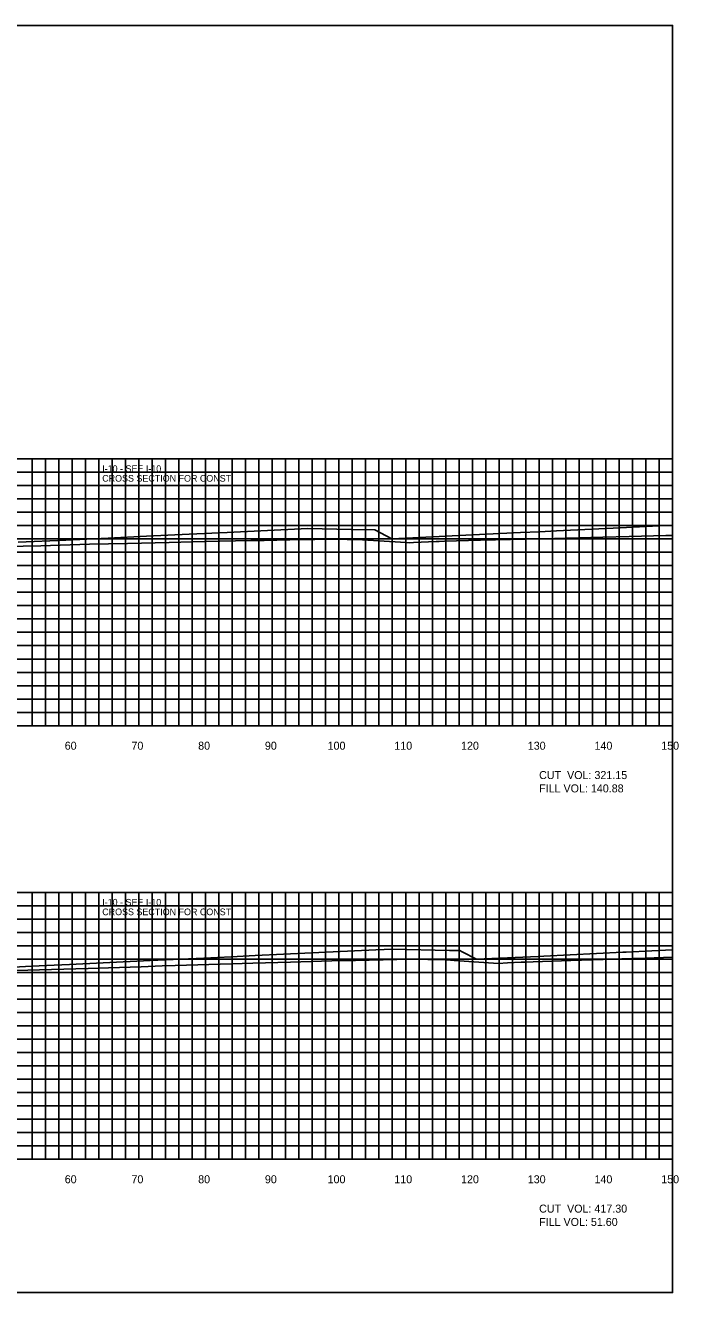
# Model space of a CAD drawing. Extents: x 1797652 to 1804159, y 242516 to 246906.
# Drawn here: x 1803717.5 to 1803815.4, y 242516 to 242706 of the extents above; entities that cross this region are included whole.
import ezdxf

# ---------------------------------------------------------------- set-up
doc = ezdxf.new("R2010")
doc.units = 0
for name, color, linetype in [('10', 7, 'Continuous'), ('3', 7, 'Continuous'), ('60', 7, 'Continuous'), ('CL-CNST', 7, 'Continuous'), ('Level 62', 7, 'Continuous'), ('M-ROADS', 7, 'Continuous')]:
    doc.layers.add(name, color=color, linetype=linetype)

msp = doc.modelspace()

# ---------------------------------------------------------------- linework, layer by layer
msp.add_lwpolyline([(1803514.49, 242516), (1803814.49, 242516), (1803814.49, 242706), (1803514.49, 242706)], close=True)
at = {"layer": '60'}
for p, q in [((1803814.49, 242601), (1803814.49, 242641)), ((1803814.55, 242641), (1803814.49, 242641)), ((1803814.55, 242631), (1803814.49, 242631)), ((1803814.55, 242621), (1803814.49, 242621)), ((1803814.55, 242611), (1803814.49, 242611)), ((1803514.49, 242601), (1803814.49, 242601)), ((1803724.49, 242600.94), (1803724.49, 242601)), ((1803734.49, 242600.94), (1803734.49, 242601)), ((1803744.49, 242600.94), (1803744.49, 242601)), ((1803754.49, 242600.94), (1803754.49, 242601)), ((1803764.49, 242600.94), (1803764.49, 242601)), ((1803774.49, 242600.94), (1803774.49, 242601)), ((1803784.49, 242600.94), (1803784.49, 242601)), ((1803794.49, 242600.94), (1803794.49, 242601)), ((1803804.49, 242600.94), (1803804.49, 242601)), ((1803814.49, 242600.94), (1803814.49, 242601)), ((1803814.55, 242601), (1803814.49, 242601)), ((1803814.49, 242536), (1803814.49, 242576)), ((1803814.55, 242576), (1803814.49, 242576)), ((1803814.55, 242566), (1803814.49, 242566)), ((1803814.55, 242556), (1803814.49, 242556)), ((1803814.55, 242546), (1803814.49, 242546)), ((1803514.49, 242536), (1803814.49, 242536)), ((1803724.49, 242535.94), (1803724.49, 242536)), ((1803734.49, 242535.94), (1803734.49, 242536)), ((1803744.49, 242535.94), (1803744.49, 242536)), ((1803754.49, 242535.94), (1803754.49, 242536)), ((1803764.49, 242535.94), (1803764.49, 242536)), ((1803774.49, 242535.94), (1803774.49, 242536)), ((1803784.49, 242535.94), (1803784.49, 242536)), ((1803794.49, 242535.94), (1803794.49, 242536)), ((1803804.49, 242535.94), (1803804.49, 242536)), ((1803814.49, 242535.94), (1803814.49, 242536)), ((1803814.55, 242536), (1803814.49, 242536))]:
    msp.add_line(p, q, dxfattribs=at)
at = {"layer": 'CL-CNST'}
for points in [[(1803716.41, 242628.5), (1803723.57, 242628.84), (1803729.92, 242629.14), (1803735.65, 242629.42), (1803742.06, 242629.72), (1803747.74, 242629.99), (1803752.78, 242630.23), (1803759.82, 242630.57), (1803766.31, 242630.42), (1803769.89, 242630.35), (1803770.73, 242629.91), (1803772.41, 242629.04), (1803775.54, 242629.19), (1803782.48, 242629.52), (1803791.69, 242629.96), (1803794.56, 242630.09), (1803797.11, 242630.22), (1803806.65, 242630.67), (1803808.56, 242630.76), (1803814.49, 242631.04)], [(1803712.02, 242564.62), (1803718.41, 242564.93), (1803724.12, 242565.2), (1803729.14, 242565.44), (1803736.22, 242565.78), (1803744.22, 242566.16), (1803748.32, 242566.35), (1803751.92, 242566.53), (1803760.42, 242566.93), (1803770.01, 242567.39), (1803772.52, 242567.51), (1803781.07, 242567.32), (1803782.6, 242567.29), (1803782.95, 242567.1), (1803785.12, 242565.98), (1803794.35, 242566.42), (1803795.2, 242566.46), (1803807.04, 242567.03), (1803807.3, 242567.04), (1803807.53, 242567.05), (1803811.36, 242567.23), (1803814.49, 242567.38)]]:
    msp.add_lwpolyline(points, dxfattribs=at)
at = {"layer": 'Level 62'}
for p, q in [((1803514.49, 242641), (1803814.49, 242641)), ((1803718.49, 242601), (1803718.49, 242641)), ((1803720.49, 242601), (1803720.49, 242641)), ((1803722.49, 242601), (1803722.49, 242641)), ((1803724.49, 242601), (1803724.49, 242641)), ((1803726.49, 242601), (1803726.49, 242641)), ((1803728.49, 242601), (1803728.49, 242641)), ((1803730.49, 242601), (1803730.49, 242641)), ((1803732.49, 242601), (1803732.49, 242641)), ((1803734.49, 242601), (1803734.49, 242641)), ((1803736.49, 242601), (1803736.49, 242641)), ((1803738.49, 242601), (1803738.49, 242641)), ((1803740.49, 242601), (1803740.49, 242641)), ((1803742.49, 242601), (1803742.49, 242641)), ((1803744.49, 242601), (1803744.49, 242641)), ((1803746.49, 242601), (1803746.49, 242641)), ((1803748.49, 242601), (1803748.49, 242641)), ((1803750.49, 242601), (1803750.49, 242641)), ((1803752.49, 242601), (1803752.49, 242641)), ((1803754.49, 242601), (1803754.49, 242641)), ((1803756.49, 242601), (1803756.49, 242641)), ((1803758.49, 242601), (1803758.49, 242641)), ((1803760.49, 242601), (1803760.49, 242641)), ((1803762.49, 242601), (1803762.49, 242641)), ((1803764.49, 242601), (1803764.49, 242641)), ((1803766.49, 242601), (1803766.49, 242641)), ((1803768.49, 242601), (1803768.49, 242641)), ((1803770.49, 242601), (1803770.49, 242641)), ((1803772.49, 242601), (1803772.49, 242641)), ((1803774.49, 242601), (1803774.49, 242641)), ((1803776.49, 242601), (1803776.49, 242641)), ((1803778.49, 242601), (1803778.49, 242641)), ((1803780.49, 242601), (1803780.49, 242641)), ((1803782.49, 242601), (1803782.49, 242641)), ((1803784.49, 242601), (1803784.49, 242641)), ((1803786.49, 242601), (1803786.49, 242641)), ((1803788.49, 242601), (1803788.49, 242641)), ((1803790.49, 242601), (1803790.49, 242641)), ((1803792.49, 242601), (1803792.49, 242641)), ((1803794.49, 242601), (1803794.49, 242641)), ((1803796.49, 242601), (1803796.49, 242641)), ((1803798.49, 242601), (1803798.49, 242641)), ((1803800.49, 242601), (1803800.49, 242641)), ((1803802.49, 242601), (1803802.49, 242641)), ((1803804.49, 242601), (1803804.49, 242641)), ((1803806.49, 242601), (1803806.49, 242641)), ((1803808.49, 242601), (1803808.49, 242641)), ((1803810.49, 242601), (1803810.49, 242641)), ((1803812.49, 242601), (1803812.49, 242641)), ((1803814.49, 242601), (1803814.49, 242641)), ((1803514.49, 242639), (1803814.49, 242639)), ((1803514.49, 242637), (1803814.49, 242637)), ((1803514.49, 242635), (1803814.49, 242635)), ((1803514.49, 242633), (1803814.49, 242633)), ((1803514.49, 242631), (1803814.49, 242631)), ((1803514.49, 242629), (1803814.49, 242629)), ((1803514.49, 242627), (1803814.49, 242627)), ((1803514.49, 242625), (1803814.49, 242625)), ((1803514.49, 242623), (1803814.49, 242623)), ((1803514.49, 242621), (1803814.49, 242621)), ((1803514.49, 242619), (1803814.49, 242619)), ((1803514.49, 242617), (1803814.49, 242617)), ((1803514.49, 242615), (1803814.49, 242615)), ((1803514.49, 242613), (1803814.49, 242613)), ((1803514.49, 242611), (1803814.49, 242611)), ((1803514.49, 242609), (1803814.49, 242609)), ((1803514.49, 242607), (1803814.49, 242607)), ((1803514.49, 242605), (1803814.49, 242605)), ((1803514.49, 242603), (1803814.49, 242603)), ((1803514.49, 242601), (1803814.49, 242601)), ((1803514.49, 242576), (1803814.49, 242576)), ((1803718.49, 242536), (1803718.49, 242576)), ((1803720.49, 242536), (1803720.49, 242576)), ((1803722.49, 242536), (1803722.49, 242576)), ((1803724.49, 242536), (1803724.49, 242576)), ((1803726.49, 242536), (1803726.49, 242576)), ((1803728.49, 242536), (1803728.49, 242576)), ((1803730.49, 242536), (1803730.49, 242576)), ((1803732.49, 242536), (1803732.49, 242576)), ((1803734.49, 242536), (1803734.49, 242576)), ((1803736.49, 242536), (1803736.49, 242576)), ((1803738.49, 242536), (1803738.49, 242576)), ((1803740.49, 242536), (1803740.49, 242576)), ((1803742.49, 242536), (1803742.49, 242576)), ((1803744.49, 242536), (1803744.49, 242576)), ((1803746.49, 242536), (1803746.49, 242576)), ((1803748.49, 242536), (1803748.49, 242576)), ((1803750.49, 242536), (1803750.49, 242576)), ((1803752.49, 242536), (1803752.49, 242576)), ((1803754.49, 242536), (1803754.49, 242576)), ((1803756.49, 242536), (1803756.49, 242576)), ((1803758.49, 242536), (1803758.49, 242576)), ((1803760.49, 242536), (1803760.49, 242576)), ((1803762.49, 242536), (1803762.49, 242576)), ((1803764.49, 242536), (1803764.49, 242576)), ((1803766.49, 242536), (1803766.49, 242576)), ((1803768.49, 242536), (1803768.49, 242576)), ((1803770.49, 242536), (1803770.49, 242576)), ((1803772.49, 242536), (1803772.49, 242576)), ((1803774.49, 242536), (1803774.49, 242576)), ((1803776.49, 242536), (1803776.49, 242576)), ((1803778.49, 242536), (1803778.49, 242576)), ((1803780.49, 242536), (1803780.49, 242576)), ((1803782.49, 242536), (1803782.49, 242576)), ((1803784.49, 242536), (1803784.49, 242576)), ((1803786.49, 242536), (1803786.49, 242576)), ((1803788.49, 242536), (1803788.49, 242576)), ((1803790.49, 242536), (1803790.49, 242576)), ((1803792.49, 242536), (1803792.49, 242576)), ((1803794.49, 242536), (1803794.49, 242576)), ((1803796.49, 242536), (1803796.49, 242576)), ((1803798.49, 242536), (1803798.49, 242576)), ((1803800.49, 242536), (1803800.49, 242576)), ((1803802.49, 242536), (1803802.49, 242576)), ((1803804.49, 242536), (1803804.49, 242576)), ((1803806.49, 242536), (1803806.49, 242576)), ((1803808.49, 242536), (1803808.49, 242576)), ((1803810.49, 242536), (1803810.49, 242576)), ((1803812.49, 242536), (1803812.49, 242576)), ((1803814.49, 242536), (1803814.49, 242576)), ((1803514.49, 242574), (1803814.49, 242574)), ((1803514.49, 242572), (1803814.49, 242572)), ((1803514.49, 242570), (1803814.49, 242570)), ((1803514.49, 242568), (1803814.49, 242568)), ((1803514.49, 242566), (1803814.49, 242566)), ((1803514.49, 242564), (1803814.49, 242564)), ((1803514.49, 242562), (1803814.49, 242562)), ((1803514.49, 242560), (1803814.49, 242560)), ((1803514.49, 242558), (1803814.49, 242558)), ((1803514.49, 242556), (1803814.49, 242556)), ((1803514.49, 242554), (1803814.49, 242554)), ((1803514.49, 242552), (1803814.49, 242552)), ((1803514.49, 242550), (1803814.49, 242550)), ((1803514.49, 242548), (1803814.49, 242548)), ((1803514.49, 242546), (1803814.49, 242546)), ((1803514.49, 242544), (1803814.49, 242544)), ((1803514.49, 242542), (1803814.49, 242542)), ((1803514.49, 242540), (1803814.49, 242540)), ((1803514.49, 242538), (1803814.49, 242538)), ((1803514.49, 242536), (1803814.49, 242536))]:
    msp.add_line(p, q, dxfattribs=at)
at = {"layer": 'M-ROADS'}
for points in [[(1803714.52, 242627.85), (1803719.8, 242627.99), (1803727.11, 242628.2), (1803732.82, 242628.33), (1803739.05, 242628.49), (1803744.32, 242628.61), (1803751.3, 242628.75), (1803753.27, 242628.79), (1803757.11, 242628.86), (1803760.89, 242628.92), (1803762.84, 242628.96), (1803763.71, 242628.96), (1803764.09, 242628.97), (1803765.71, 242628.92), (1803768, 242628.85), (1803773.72, 242628.52), (1803775.1, 242628.44), (1803775.66, 242628.46), (1803779.04, 242628.62), (1803779.5, 242628.64), (1803780.3, 242628.66), (1803785.71, 242628.81), (1803792.46, 242628.96), (1803796.8, 242629.08), (1803804.06, 242629.28), (1803808, 242629.38), (1803813.46, 242629.52), (1803814.49, 242629.54)], [(1803716.06, 242564.32), (1803721.42, 242564.45), (1803726.91, 242564.59), (1803729.97, 242564.68), (1803734.85, 242564.86), (1803737.97, 242564.98), (1803739.94, 242565.04), (1803748.38, 242565.3), (1803751.57, 242565.39), (1803757.24, 242565.54), (1803763.42, 242565.74), (1803766.97, 242565.81), (1803775.24, 242565.99), (1803775.96, 242565.99), (1803776.51, 242565.99), (1803777.83, 242565.96), (1803780.64, 242565.88), (1803781.78, 242565.81), (1803788.38, 242565.37), (1803789.77, 242565.43), (1803791.81, 242565.53), (1803792.32, 242565.55), (1803792.55, 242565.56), (1803793.59, 242565.61), (1803799.24, 242565.8), (1803805.73, 242566), (1803806.88, 242566.04), (1803810.38, 242566.15), (1803814.49, 242566.28)]]:
    msp.add_lwpolyline(points, dxfattribs=at)

# ---------------------------------------------------------------- texts
at = {"layer": '10'}
for s, p in [('60', (1803723.39, 242597.4)), ('70', (1803733.39, 242597.4)), ('80', (1803743.39, 242597.4)), ('90', (1803753.39, 242597.4)), ('100', (1803762.79, 242597.4)), ('110', (1803772.79, 242597.4)), ('120', (1803782.79, 242597.4)), ('130', (1803792.79, 242597.4)), ('140', (1803802.79, 242597.4)), ('150', (1803812.79, 242597.4)), ('CUT  VOL: 321.15', (1803794.49, 242593)), ('FILL VOL: 140.88', (1803794.49, 242591)), ('60', (1803723.39, 242532.4)), ('70', (1803733.39, 242532.4)), ('80', (1803743.39, 242532.4)), ('90', (1803753.39, 242532.4)), ('100', (1803762.79, 242532.4)), ('110', (1803772.79, 242532.4)), ('120', (1803782.79, 242532.4)), ('130', (1803792.79, 242532.4)), ('140', (1803802.79, 242532.4)), ('150', (1803812.79, 242532.4)), ('CUT  VOL: 417.30', (1803794.49, 242528)), ('FILL VOL: 51.60', (1803794.49, 242526))]:
    msp.add_text(s, height=1.2, dxfattribs=at).set_placement(p)
at = {"layer": '3'}
for s, p in [('I-10 - SEE I-10', (1803729.01, 242639.03)), ('CROSS SECTION FOR CONST ', (1803729.01, 242637.59)), ('I-10 - SEE I-10', (1803729.01, 242574.03)), ('CROSS SECTION FOR CONST ', (1803729.01, 242572.59))]:
    msp.add_text(s, height=1, dxfattribs=at).set_placement(p)

doc.saveas('drawing.dxf')
